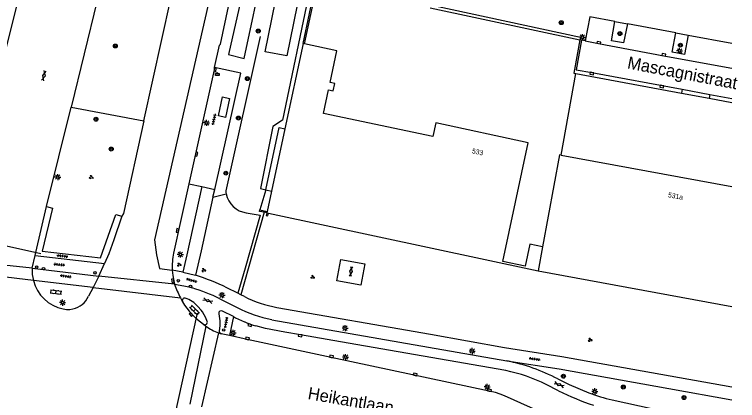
# Model space of a CAD drawing. Extents: x 130998 to 133001, y 398999 to 403002.
# Drawn here: x 132854 to 133001.2, y 399481.4 to 399559.9 of the extents above; entities that cross this region are included whole.
import ezdxf

# ---------------------------------------------------------------- set-up
doc = ezdxf.new("R2010")
doc.units = 0
for name, color, linetype in [('gg-afsc-hekwerk', 7, 'Continuous'), ('gg-afsc-muur', 7, 'Continuous'), ('gg-anno-huisnummerreeks BGT', 7, 'Continuous'), ('gg-anno-openbare ruimte label', 7, 'Continuous'), ('gg-bbg-abri', 7, 'Continuous'), ('gg-bbg-hoofdgebouw', 7, 'Continuous'), ('gg-bbg-tussenscheiding', 7, 'Continuous'), ('gg-knt-bovenkant onderkant talud', 7, 'Continuous'), ('gg-knt-verharding', 7, 'Continuous'), ('gg-knt-verharding nz', 7, 'Continuous'), ('gg-kntw-bovenkant insteek waterloop', 7, 'Continuous'), ('gt-grn-groengrens', 7, 'Continuous'), ('gt-grn-weggrens', 7, 'Continuous'), ('gt-knt-lijn portaal', 7, 'Continuous'), ('gt-symb-afvalbak', 7, 'Continuous'), ('gt-symb-boom', 7, 'Continuous'), ('gt-symb-drukknoppaal', 7, 'Continuous'), ('gt-symb-gesloten verharding', 7, 'Continuous'), ('gt-symb-groenvak', 7, 'Continuous'), ('gt-symb-klinker verharding', 7, 'Continuous'), ('gt-symb-kolk', 7, 'Continuous'), ('gt-symb-lichtmast', 7, 'Continuous'), ('gt-symb-tegel verharding', 7, 'Continuous'), ('gt-symb-verkeersregelinstallatiepaal', 7, 'Continuous')]:
    doc.layers.add(name, color=color, linetype=linetype)

# ---------------------------------------------------------------- blocks, each defined once
blk = doc.blocks.new('gt0-LMAST')
at = {"layer": 'gt-symb-lichtmast'}
for p, q in [((-0.18, 0.17), (-0.45, 0.44)), ((-0.01, 0.25), (-0.01, 0.62)), ((0.17, 0.17), (0.44, 0.44)), ((-0.26, 0), (-0.63, 0)), ((-0.18, -0.18), (-0.45, -0.45)), ((-0.01, -0.25), (-0.01, -0.63)), ((0.44, -0.45), (0.17, -0.18)), ((0.24, 0), (0.62, 0))]:
    blk.add_line(p, q, dxfattribs=at)
blk.add_circle((-0.01, 0), 0.25, dxfattribs=at)
blk = doc.blocks.new('gt0-BOOM')
at = {"layer": 'gt-symb-boom'}
for radius in [0.4, 0.2]:
    blk.add_circle((0, 0), radius, dxfattribs=at)
blk = doc.blocks.new('gt0-KOLK')
at = {"layer": 'gt-symb-kolk'}
blk.add_lwpolyline([(0, 0), (0.37, 0), (0.37, 0.4), (-0.38, 0.4), (-0.38, 0), (0, 0)], dxfattribs=at)
blk = doc.blocks.new('gt0-TEG1')
at = {"layer": 'gt-symb-tegel verharding'}
for p, q in [((-1.12, 0), (1.12, 0)), ((-0.9, -0.25), (-0.9, 0.25)), ((-0.45, -0.25), (-0.45, 0.25)), ((0, -0.25), (0, 0.25)), ((0.45, -0.25), (0.45, 0.25)), ((0.9, -0.25), (0.9, 0.25))]:
    blk.add_line(p, q, dxfattribs=at)
blk = doc.blocks.new('gt0-GESVH1')
at = {"layer": 'gt-symb-gesloten verharding'}
for p, q in [((-0.99, -0.26), (0.01, 0.24)), ((0.01, -0.26), (-0.99, 0.24)), ((0.01, 0.24), (1.01, -0.26)), ((1.01, 0.24), (0.01, -0.26))]:
    blk.add_line(p, q, dxfattribs=at)
blk = doc.blocks.new('gt0-GRVAK')
at = {"layer": 'gt-symb-groenvak'}
for p, q in [((-0.11, 0.19), (-0.23, 0.24)), ((-0.18, 0.15), (0.09, 0.15)), ((-0.09, 0.21), (-0.16, 0.32)), ((-0.05, 0.21), (-0.05, 0.39)), ((0, 0.21), (0.06, 0.32)), ((0.01, 0.19), (0.13, 0.24)), ((0.26, -0.05), (0.2, 0.06)), ((0.3, -0.05), (0.3, 0.13)), ((0.35, -0.05), (0.41, 0.06)), ((-0.24, -0.23), (-0.36, -0.18)), ((-0.32, -0.26), (-0.05, -0.26)), ((-0.23, -0.21), (-0.29, -0.09)), ((-0.18, -0.2), (-0.18, -0.02)), ((-0.14, -0.21), (-0.07, -0.09)), ((-0.12, -0.23), (0, -0.18)), ((0.24, -0.07), (0.12, -0.02)), ((0.17, -0.11), (0.44, -0.11)), ((0.37, -0.07), (0.49, -0.02))]:
    blk.add_line(p, q, dxfattribs=at)
blk = doc.blocks.new('gt0-VIPAAL')
at = {"layer": 'gt-symb-verkeersregelinstallatiepaal'}
blk.add_circle((0, 0), 0.25, dxfattribs=at)
blk = doc.blocks.new('gt0-KL1')
at = {"layer": 'gt-symb-klinker verharding'}
for p, q in [((-1.15, 0.3), (1.15, 0.3)), ((-1, -0.3), (-1, 0.3)), ((-0.5, 0.3), (-0.5, 0.45)), ((0, -0.3), (0, 0.3)), ((0.5, 0.3), (0.5, 0.45)), ((1, -0.3), (1, 0.3)), ((-1.15, -0.3), (1.15, -0.3)), ((-0.5, -0.45), (-0.5, -0.3)), ((0.5, -0.45), (0.5, -0.3))]:
    blk.add_line(p, q, dxfattribs=at)
blk = doc.blocks.new('gt0-ABAK')
at = {"layer": 'gt-symb-afvalbak'}
blk.add_lwpolyline([(0.38, -0.5), (-0.37, -0.5), (-0.37, -0.1), (0.38, -0.1)], close=True, dxfattribs=at)
blk.add_circle((0, 0), 0.1, dxfattribs=at)
blk = doc.blocks.new('gt0-DPAAL')
at = {"layer": 'gt-symb-drukknoppaal'}
blk.add_circle((0, 0), 0.25, dxfattribs=at)

msp = doc.modelspace()

# ---------------------------------------------------------------- linework, layer by layer
at = {"layer": 'gg-afsc-hekwerk'}
for p, q in [((132938.59, 399561.3), (132969.12, 399554.73)), ((132965.26, 399531.32), (132968.26, 399547.9)), ((132968.26, 399547.9), (132989.79, 399543.92)), ((132989.79, 399543.92), (132995.41, 399542.89)), ((132995.41, 399542.89), (133000, 399542.04))]:
    msp.add_line(p, q, dxfattribs=at)
msp.add_lwpolyline([(132969.12, 399554.73), (132967.89, 399547.96), (132968.26, 399547.9)], dxfattribs=at)
at = {"layer": 'gg-afsc-muur'}
for p, q in [((132903.96, 399520.16), (132905.43, 399519.84)), ((132905.36, 399519.55), (132904.79, 399519.67))]:
    msp.add_line(p, q, dxfattribs=at)
for points in [[(132912.75, 399553.99), (132915.35, 399566.29), (132917.54, 399565.84)], [(132913.05, 399553.93), (132915.59, 399565.92), (132927.92, 399563.37), (132927.97, 399563.58)], [(132904.79, 399519.67), (132903.9, 399519.86), (132903.96, 399520.16)], [(132905.36, 399519.55), (132905.25, 399519.04), (132905.59, 399518.96), (132905.7, 399519.48)]]:
    msp.add_lwpolyline(points, dxfattribs=at)
at = {"layer": 'gg-bbg-abri'}
msp.add_lwpolyline([(132896.32, 399543.15), (132897.75, 399542.82), (132896.93, 399538.99), (132895.5, 399539.32), (132896.32, 399543.15)], dxfattribs=at)
at = {"layer": 'gg-bbg-hoofdgebouw'}
for p, q in [((132912.75, 399553.99), (132909.04, 399536.68)), ((132913.05, 399553.93), (132912.75, 399553.99)), ((132909.04, 399536.68), (132906.31, 399523.98)), ((132965.26, 399531.32), (133000, 399524.95)), ((132906.31, 399523.98), (132905.43, 399519.84)), ((132905.43, 399519.84), (132905.36, 399519.55)), ((132905.36, 399519.55), (132905.7, 399519.48)), ((132905.7, 399519.48), (132960.59, 399507.76)), ((132960.59, 399507.76), (133000, 399500.53))]:
    msp.add_line(p, q, dxfattribs=at)
for points in [[(132961.48, 399512.64), (132958.91, 399513.16), (132957.94, 399508.72), (132953.4, 399509.68), (132958.58, 399533.83), (132939.76, 399537.88), (132939.15, 399535.06), (132916.88, 399539.74), (132917.94, 399544.57), (132918.9, 399544.38), (132919.24, 399545.87), (132918.27, 399546.07), (132919.62, 399552.52), (132913.05, 399553.93)], [(132965.26, 399531.32), (132964.92, 399531.38), (132961.48, 399512.64)]]:
    msp.add_lwpolyline(points, dxfattribs=at)
at = {"layer": 'gg-bbg-tussenscheiding'}
msp.add_line((132961.48, 399512.64), (132960.59, 399507.76), dxfattribs=at)
at = {"layer": 'gg-knt-bovenkant onderkant talud'}
for p, q in [((132904.03, 399555.43), (132897.02, 399524.05)), ((132901.19, 399519.58), (132903.99, 399519.1))]:
    msp.add_line(p, q, dxfattribs=at)
msp.add_lwpolyline([(132897.02, 399524.05), (132897.05, 399523.72), (132897.1, 399523.4)], dxfattribs=at)
msp.add_arc((132901.75, 399524.28), 4.73, 190.7342, 263.1907, dxfattribs=at)
at = {"layer": 'gg-knt-verharding'}
for p, q in [((132988.65, 399556.19), (132978.77, 399558.03)), ((132969.43, 399554.67), (132969.12, 399554.73)), ((132970.2, 399554.53), (132969.43, 399554.67)), ((132991.16, 399555.73), (133000, 399554.11)), ((132989.93, 399544.69), (132995.55, 399543.64)), ((132995.55, 399543.64), (133000, 399542.81)), ((132860.52, 399520.82), (132865.5, 399541.05)), ((132889.49, 399525.48), (132886.35, 399511.39)), ((132889.49, 399525.48), (132892.11, 399524.89)), ((132894.4, 399522.73), (132894.76, 399524.3)), ((132905.17, 399524.27), (132906.31, 399523.98)), ((132858.33, 399511.51), (132860.52, 399520.82)), ((132857.61, 399508.28), (132858.18, 399510.87)), ((132858.18, 399510.87), (132858.33, 399511.51)), ((132858.18, 399510.87), (132872.33, 399509.24)), ((132871.18, 399506.7), (132872.33, 399509.24)), ((132857.61, 399508.28), (132871.18, 399506.7)), ((132888.29, 399507.46), (132886.12, 399507.89)), ((132871.18, 399506.7), (132870.01, 399504.39)), ((132870.01, 399504.39), (132857.86, 399505.8)), ((132870.01, 399504.39), (132869.06, 399502.6)), ((132899.45, 399503.2), (132897.24, 399504.3)), ((132900.04, 399502.9), (132899.45, 399503.2)), ((132895.78, 399502.08), (132899.33, 399500.29)), ((132900.81, 399502.51), (132900.04, 399502.9)), ((132888.2, 399501.47), (132888.16, 399501.55)), ((132898.57, 399498.44), (132896.32, 399499.56)), ((132898.57, 399498.44), (132897.74, 399494.59)), ((132906.36, 399497.82), (132954.23, 399489.43)), ((132892.46, 399496.9), (132892.58, 399496.83)), ((132896.04, 399494.97), (132895.87, 399495.05)), ((132897.74, 399494.59), (132896.04, 399494.97)), ((132964.75, 399483.38), (132962.26, 399484.64)), ((132975.65, 399481.53), (133000, 399476.23))]:
    msp.add_line(p, q, dxfattribs=at)
for points in [[(132844.07, 399518.96), (132846.11, 399527.65), (132847.38, 399532.75), (132851.98, 399551.67), (132857.77, 399574.97), (132861.41, 399589.44), (132866.24, 399608.29), (132874.84, 399642.05)], [(132890.29, 399638.14), (132882, 399605.97), (132881.4, 399606.05), (132870.83, 399562.74), (132865.5, 399541.05)], [(132880.33, 399538.3), (132885.79, 399563.16), (132901.97, 399635.19)], [(132914.06, 399564.8), (132908.58, 399538.39), (132906.57, 399537.15), (132904.11, 399524.54), (132905.17, 399524.27)], [(132894.69, 399549.14), (132895.74, 399553.66), (132895.93, 399553.91), (132897.57, 399561.55)], [(132976.23, 399558.49), (132971.1, 399559.45), (132970.2, 399554.53)], [(132978.77, 399558.03), (132978.01, 399554.12), (132975.5, 399554.56), (132976.23, 399558.49)], [(132991.16, 399555.73), (132990.42, 399551.8), (132987.91, 399552.27), (132988.65, 399556.19)], [(132969.43, 399554.67), (132968.35, 399548.68), (132971.54, 399548.13), (132989.93, 399544.69)], [(132894.69, 399549.14), (132894.62, 399548.66), (132889.49, 399525.48)], [(132894.76, 399524.3), (132900.05, 399547.97), (132894.69, 399549.14)], [(132880.33, 399538.3), (132876.2, 399519.43), (132875.88, 399518.91)], [(132905.17, 399524.27), (132907.9, 399536.92), (132909.04, 399536.68)], [(132892.11, 399524.89), (132889.1, 399511.05), (132888.29, 399507.46)], [(132894.4, 399522.73), (132891.99, 399511.85), (132890.85, 399506.88)], [(132860.52, 399520.82), (132861.73, 399520.53), (132859.66, 399511.74), (132871.48, 399510.38), (132874.64, 399519.2), (132875.88, 399518.91)], [(132875.88, 399518.91), (132874.21, 399514.04), (132873.17, 399511.22), (132872.33, 399509.24)], [(132925.31, 399509.18), (132924.52, 399504.86), (132919.65, 399505.75), (132920.43, 399510.07), (132925.31, 399509.18)], [(132886.12, 399507.89), (132886.24, 399506.8), (132886.42, 399505.74), (132886.57, 399505.03)], [(132886.57, 399505.03), (132888.49, 399504.69), (132889.46, 399504.49), (132890.18, 399504.3)], [(132893.23, 399497.46), (132892.92, 399498.2), (132892.24, 399499.4), (132891.99, 399499.73), (132891.34, 399500.51)], [(132907.43, 399500.32), (132938.7, 399494.85), (132953.73, 399492.19), (132965.44, 399490.32), (133000, 399484.13)], [(132863.88, 399500), (132864.61, 399499.89), (132865.25, 399499.9), (132865.89, 399500)], [(132895.59, 399499.04), (132895.67, 399498.56), (132895.79, 399497.56), (132895.78, 399496.55), (132895.64, 399495.55), (132895.65, 399495.35), (132895.73, 399495.18), (132895.87, 399495.05)], [(132898.57, 399498.44), (132898.99, 399498.2), (132900.85, 399497.38)], [(132954.01, 399487.46), (132920.33, 399493.33), (132912.2, 399494.77), (132909.01, 399495.31), (132905.07, 399496.03), (132903.14, 399496.55)], [(132971.5, 399474.36), (132967.67, 399476.09), (132953.77, 399482.32), (132952.85, 399482.68), (132951.9, 399482.98), (132950.66, 399483.28), (132918.48, 399490.15), (132901.37, 399493.79), (132897.74, 399494.59)], [(132954.23, 399489.43), (132964.88, 399487.82), (132987.18, 399483.79), (133000, 399481.49)], [(132964.59, 399485.77), (132966.9, 399484.63), (132970.93, 399482.92)]]:
    msp.add_lwpolyline(points, dxfattribs=at)
for centre, radius, start, end in [((132899.87, 399508.75), 13.77, 168.9565, 183.5934), ((132864.04, 399507.68), 6.46, 174.6649, 196.9347), ((132878.05, 399465.93), 42.9, 63.4354, 72.6499), ((132865.45, 399507.66), 7.81, 193.7634, 258.4277), ((132876.89, 399462.5), 43.86, 64.4929, 72.3571), ((132864.85, 399504.51), 4.63, 283.0442, 335.6113), ((132888.65, 399501.72), 0.514, 143.7012, 199.5671), ((132888.65, 399501.72), 0.512, 77.6044, 143.5558), ((132886.99, 399496.75), 5.75, 40.8968, 72.1839), ((132911.56, 399523.83), 23.88, 243.2435, 260.0269), ((132901.7, 399509.78), 15.85, 211.6157, 234.3513), ((132911.76, 399524.47), 27.18, 242.7837, 258.5426), ((132896.08, 399499.13), 0.498, 60.8946, 189.9142), ((132892.76, 399497.3), 0.499, 305.8991, 18.7588), ((132907.29, 399511.52), 15.53, 245.5349, 254.531), ((132892.76, 399497.3), 0.497, 249.3129, 306.0207), ((132947.26, 399453.17), 36.92, 62.0095, 79.1104), ((132947.73, 399455.66), 32.41, 63.3752, 78.8409), ((132991.57, 399537.62), 60.51, 243.6887, 251.0019), ((132983.42, 399516.59), 35.91, 249.6504, 257.5088)]:
    msp.add_arc(centre, radius, start, end, dxfattribs=at)
at = {"layer": 'gg-knt-verharding nz'}
for p, q in [((132892.11, 399524.89), (132894.76, 399524.3)), ((132857.61, 399508.28), (132836.08, 399510.69)), ((132857.86, 399505.8), (132841.4, 399507.69)), ((132886.57, 399505.03), (132871.18, 399506.7)), ((132870.01, 399504.39), (132887.8, 399502.24)), ((132887.8, 399502.24), (132888.2, 399501.47)), ((132892.98, 399496.5), (132889.68, 399480.63)), ((132892.46, 399496.9), (132892.98, 399496.5)), ((132895.51, 399495.14), (132892.06, 399480.08)), ((132895.51, 399495.14), (132896.04, 399494.97))]:
    msp.add_line(p, q, dxfattribs=at)
for points in [[(132902.6, 399602.09), (132882.51, 399514.08), (132882.88, 399511.01), (132883.54, 399508.27), (132886.12, 399507.89)], [(132970.2, 399554.53), (132972.9, 399553.99), (132986.18, 399551.52), (133000, 399548.98)]]:
    msp.add_lwpolyline(points, dxfattribs=at)
for centre, radius, start, end in [((132913.13, 399515.06), 28.4, 200.6878, 206.8442), ((132898.95, 399504.62), 10.08, 233.6869, 250.0577)]:
    msp.add_arc(centre, radius, start, end, dxfattribs=at)
at = {"layer": 'gg-kntw-bovenkant insteek waterloop'}
msp.add_lwpolyline([(132915.45, 399631.79), (132904.85, 399583.79), (132897.54, 399551.75), (132900.72, 399550.96), (132904.75, 399569.72)], dxfattribs=at)
at = {"layer": 'gt-grn-groengrens'}
for p, q in [((132976.23, 399558.49), (132978.77, 399558.03)), ((132988.65, 399556.19), (132991.16, 399555.73)), ((132989.93, 399544.69), (132989.79, 399543.92)), ((132995.55, 399543.64), (132995.41, 399542.89)), ((132865.5, 399541.05), (132880.33, 399538.3)), ((132905.17, 399524.27), (132903.96, 399520.16)), ((132894.4, 399522.73), (132897.1, 399523.4)), ((132904.79, 399519.67), (132900.04, 399502.9))]:
    msp.add_line(p, q, dxfattribs=at)
for points in [[(132914.06, 399564.8), (132912.24, 399565.2), (132909.47, 399551.49), (132905.06, 399552.31), (132907.81, 399566.01), (132904.59, 399566.63), (132905.24, 399569.61)], [(132938.7, 399561.89), (132969.25, 399555.31), (132969.12, 399554.73)], [(132903.99, 399519.1), (132900.93, 399508.32), (132899.45, 399503.2)]]:
    msp.add_lwpolyline(points, dxfattribs=at)
at = {"layer": 'gt-grn-weggrens'}
msp.add_line((132888.29, 399507.46), (132890.85, 399506.88), dxfattribs=at)
at = {"layer": 'gt-knt-lijn portaal'}
for p, q in [((132842, 399515.18), (132859.33, 399511.28)), ((132886.64, 399478.2), (132891.24, 399499.17))]:
    msp.add_line(p, q, dxfattribs=at)

# ---------------------------------------------------------------- block references
at = {"layer": 'gt-symb-afvalbak'}
msp.add_blockref('gt0-ABAK', (132895.27, 399548.01), dxfattribs=at)
at = {"layer": 'gt-symb-boom'}
for p in [(132965.31, 399558.25), (132903.62, 399556.55), (132874.52, 399553.51), (132901.4, 399546.88), (132870.58, 399538.61), (132899.59, 399538.85), (132873.68, 399532.54), (132897.02, 399527.63), (132965.74, 399486.32), (132977.94, 399484.12), (132990.3, 399481.98)]:
    msp.add_blockref('gt0-BOOM', p, dxfattribs=at)
for p, rotation in [((132977.24, 399556.03), -100.78161673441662), ((132989.57, 399553.68), -100.78161673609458)]:
    msp.add_blockref('gt0-BOOM', p, dxfattribs=dict(at, rotation=rotation))
at = {"layer": 'gt-symb-drukknoppaal'}
for p in [(132859.9, 399508.19), (132889.83, 399504.59)]:
    msp.add_blockref('gt0-DPAAL', p, dxfattribs=at)
at = {"layer": 'gt-symb-gesloten verharding'}
for p, rotation in [((132859.97, 399547.45), 76.17220496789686), ((132922.51, 399507.64), 82.06444963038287), ((132893.36, 399501.67), 158.9542591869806), ((132964.85, 399484.62), -22.897591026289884)]:
    msp.add_blockref('gt0-GESVH1', p, dxfattribs=dict(at, rotation=rotation))
at = {"layer": 'gt-symb-groenvak', "rotation": -10.30997039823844}
for p in [(132869.61, 399526.82), (132914.68, 399506.51)]:
    msp.add_blockref('gt0-GRVAK', p, dxfattribs=at)
at = {"layer": 'gt-symb-groenvak'}
for p in [(132887.51, 399509.03), (132892.5, 399507.9), (132971.17, 399493.72)]:
    msp.add_blockref('gt0-GRVAK', p, dxfattribs=at)
at = {"layer": 'gt-symb-klinker verharding'}
for p, rotation in [((132862.44, 399503.45), -6.3718224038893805), ((132890.65, 399499.75), -44.270673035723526)]:
    msp.add_blockref('gt0-KL1', p, dxfattribs=dict(at, rotation=rotation))
at = {"layer": 'gt-symb-kolk'}
for p, rotation in [((132972.9, 399553.99), -10.5581871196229), ((132986.18, 399551.52), -10.393619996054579), ((132894.62, 399548.66), -98.39757257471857), ((132971.54, 399548.13), 170.20785375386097), ((132985.79, 399545.44), 169.34163849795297), ((132890.83, 399531.54), -102.35482691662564), ((132887.37, 399515.91), 77.58922528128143), ((132886.42, 399505.74), 99.26452398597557), ((132890.07, 399499.01), 132.85190842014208), ((132901.98, 399496.92), 160.00710602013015), ((132912.2, 399494.77), 170.49998940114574), ((132901.37, 399493.79), -11.998379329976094), ((132918.48, 399490.15), -12.080667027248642), ((132935.55, 399486.5), -12.01584508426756), ((132950.66, 399483.28), -13.895318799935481)]:
    msp.add_blockref('gt0-KOLK', p, dxfattribs=dict(at, rotation=rotation))
at = {"layer": 'gt-symb-lichtmast'}
for p in [(132969.62, 399555.31), (132989.4, 399552.52), (132893.1, 399537.86), (132862.8, 399526.84), (132887.75, 399511.09), (132896.25, 399502.82), (132863.79, 399501.3), (132898.5, 399495.15), (132921.3, 399496.1), (132947.17, 399491.45), (132921.39, 399490.22), (132950.24, 399484.14), (132972.14, 399483.24)]:
    msp.add_blockref('gt0-LMAST', p, dxfattribs=at)
at = {"layer": 'gt-symb-tegel verharding'}
for p, rotation in [((132894.58, 399538.58), -102.59095061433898), ((132863.74, 399510.76), 172.9957407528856), ((132863.13, 399509.03), -5.220361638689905), ((132864.41, 399506.65), 172.53402593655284), ((132890.06, 399505.86), -16.386305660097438), ((132897.08, 399497.24), 79.51061018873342), ((132959.9, 399489.83), -9.556527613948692)]:
    msp.add_blockref('gt0-TEG1', p, dxfattribs=dict(at, rotation=rotation))
at = {"layer": 'gt-symb-verkeersregelinstallatiepaal'}
msp.add_blockref('gt0-VIPAAL', (132858.49, 399508.53), dxfattribs=at)
for p, rotation in [((132870.37, 399507.36), 78.02530296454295), ((132887.33, 399505.74), 78.02530296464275), ((132896.58, 399495.73), 76.54507187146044)]:
    msp.add_blockref('gt0-VIPAAL', p, dxfattribs=dict(at, rotation=rotation))

# ---------------------------------------------------------------- texts
at = {"layer": 'gg-anno-huisnummerreeks BGT'}
for s, rotation, p in [('533', 347.9, (132947.05, 399531.71)), ('531a', 349.6, (132986.98, 399522.76))]:
    msp.add_text(s, height=1, rotation=rotation, dxfattribs=at).set_placement(p)
at = {"layer": 'gg-anno-openbare ruimte label'}
for s, rotation, p in [('Mascagnistraat', 349.1, (132978.62, 399548.97)), ('Heikantlaan', 350.1, (132913.58, 399481.69))]:
    msp.add_text(s, height=2.5, rotation=rotation, dxfattribs=at).set_placement(p)

doc.saveas('drawing.dxf')
